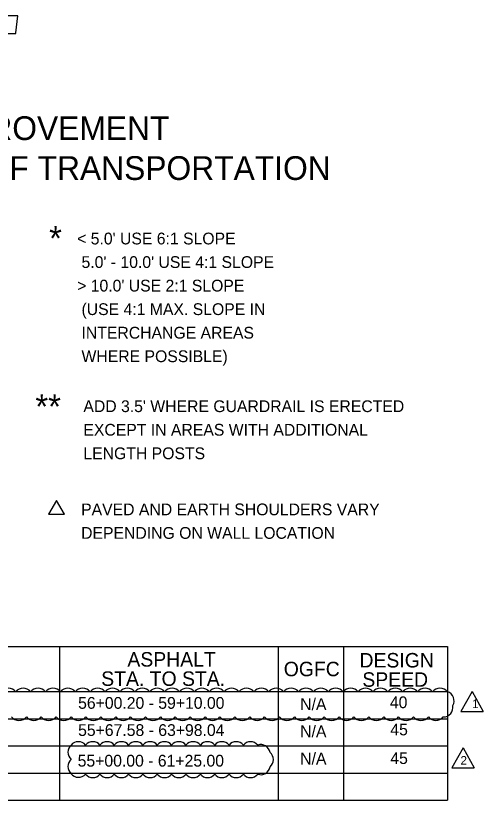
# Model space of a CAD drawing. Extents: x 5017 to 5774, y 4942 to 5266.
# Drawn here: x 5193.4 to 5241, y 5136.1 to 5216.1 of the extents above; entities that cross this region are included whole.
import ezdxf

# ---------------------------------------------------------------- set-up
doc = ezdxf.new("R2010")
doc.units = 0
for name, color, linetype in [('Level 40', 7, 'Continuous'), ('RD_SHT_Logo', 7, 'Continuous'), ('RD_SHT_TX', 7, 'Continuous'), ('RD_TX_TypSect', 7, 'Continuous')]:
    doc.layers.add(name, color=color, linetype=linetype)

msp = doc.modelspace()

# ---------------------------------------------------------------- linework, layer by layer
at = {"layer": 'Level 40'}
for p, q in [((5144.352, 5151.793), (5237.351, 5151.793)), ((5197.821, 5151.793), (5197.821, 5147.178)), ((5220.101, 5151.793), (5220.101, 5147.178)), ((5226.762, 5151.793), (5226.762, 5147.178)), ((5237.351, 5151.793), (5237.351, 5147.178))]:
    msp.add_line(p, q, dxfattribs=at)
at = {"layer": 'RD_SHT_Logo'}
msp.add_lwpolyline([(5192.072, 5214.257), (5193.325, 5214.257), (5193.369, 5214.271), (5193.383, 5214.286), (5193.383, 5214.329), (5193.602, 5216.077), (5193.602, 5216.077), (5193.573, 5216.077), (5193.558, 5216.077), (5193.442, 5216.063), (5193.281, 5216.063), (5188.635, 5216.048), (5188.547, 5216.048), (5188.533, 5216.048), (5188.518, 5216.034), (5188.504, 5215.975), (5188.343, 5215.276), (5188.125, 5214.286)], dxfattribs=at)
at = {"layer": 'RD_SHT_TX'}
for p, q in [((5239.849, 5147.201), (5238.71, 5145.171)), ((5239.849, 5147.201), (5240.987, 5145.171)), ((5238.71, 5145.171), (5240.987, 5145.171)), ((5238.926, 5141.437), (5237.787, 5139.408)), ((5238.926, 5141.437), (5240.065, 5139.408)), ((5237.787, 5139.408), (5240.065, 5139.408))]:
    msp.add_line(p, q, dxfattribs=at)
for centre, radius, start, end in [((5192.614, 5146.532), 0.989, 40, 140), ((5194.13, 5146.532), 0.989, 40, 140), ((5195.646, 5146.532), 0.989, 40, 140), ((5197.162, 5146.532), 0.989, 40, 140), ((5198.678, 5146.532), 0.989, 40, 140), ((5200.194, 5146.532), 0.989, 40, 140), ((5201.709, 5146.532), 0.989, 40, 140), ((5203.225, 5146.532), 0.989, 40, 140), ((5204.741, 5146.532), 0.989, 40, 140), ((5206.257, 5146.532), 0.989, 40, 140), ((5207.773, 5146.532), 0.989, 40, 140), ((5209.289, 5146.532), 0.989, 40, 140), ((5210.805, 5146.532), 0.989, 40, 140), ((5212.321, 5146.532), 0.989, 40, 140), ((5213.837, 5146.532), 0.989, 40, 140), ((5215.352, 5146.532), 0.989, 40, 140), ((5216.868, 5146.532), 0.989, 40, 140), ((5218.384, 5146.532), 0.989, 40, 140), ((5219.9, 5146.532), 0.989, 40, 140), ((5221.416, 5146.532), 0.989, 40, 140), ((5222.932, 5146.532), 0.989, 40, 140), ((5224.448, 5146.532), 0.989, 40, 140), ((5225.964, 5146.532), 0.989, 40, 140), ((5227.48, 5146.532), 0.989, 40, 140), ((5228.995, 5146.532), 0.989, 40, 140), ((5230.511, 5146.532), 0.989, 40, 140), ((5232.027, 5146.532), 0.989, 40, 140), ((5233.543, 5146.532), 0.989, 40, 140), ((5235.059, 5146.532), 0.989, 40, 140), ((5236.575, 5146.532), 0.989, 40, 140), ((5237.02, 5146.23), 0.989, 331.53931, 71.53931), ((5236.914, 5145.591), 0.989, 269.75671, 9.75671), ((5193.707, 5145.237), 0.989, 220, 320), ((5195.223, 5145.237), 0.989, 220, 320), ((5196.739, 5145.237), 0.989, 220, 320), ((5198.255, 5145.237), 0.989, 220, 320), ((5199.77, 5145.237), 0.989, 220, 320), ((5201.286, 5145.237), 0.989, 220, 320), ((5202.802, 5145.237), 0.989, 220, 320), ((5204.318, 5145.237), 0.989, 220, 320), ((5205.834, 5145.237), 0.989, 220, 320), ((5207.35, 5145.237), 0.989, 220, 320), ((5208.866, 5145.237), 0.989, 220, 320), ((5210.382, 5145.237), 0.989, 220, 320), ((5211.898, 5145.237), 0.989, 220, 320), ((5213.413, 5145.237), 0.989, 220, 320), ((5214.929, 5145.237), 0.989, 220, 320), ((5216.445, 5145.237), 0.989, 220, 320), ((5217.961, 5145.237), 0.989, 220, 320), ((5219.477, 5145.237), 0.989, 220, 320), ((5220.993, 5145.237), 0.989, 220, 320), ((5222.509, 5145.237), 0.989, 220, 320), ((5224.025, 5145.237), 0.989, 220, 320), ((5225.541, 5145.237), 0.989, 220, 320), ((5227.056, 5145.237), 0.989, 220, 320), ((5228.572, 5145.237), 0.989, 220, 320), ((5230.088, 5145.237), 0.989, 220, 320), ((5231.604, 5145.237), 0.989, 220, 320), ((5233.12, 5145.237), 0.989, 220, 320), ((5234.636, 5145.237), 0.989, 220, 320), ((5236.152, 5145.237), 0.989, 220, 320), ((5199.635, 5141), 0.954, 130, 230), ((5199.752, 5141.118), 0.954, 40, 140), ((5201.214, 5141.118), 0.954, 40, 140), ((5202.675, 5141.118), 0.954, 40, 140), ((5204.136, 5141.118), 0.954, 40, 140), ((5205.598, 5141.118), 0.954, 40, 140), ((5207.059, 5141.118), 0.954, 40, 140), ((5208.521, 5141.118), 0.954, 40, 140), ((5209.982, 5141.118), 0.954, 40, 140), ((5211.443, 5141.118), 0.954, 40, 140), ((5212.905, 5141.118), 0.954, 40, 140), ((5214.366, 5141.118), 0.954, 40, 140), ((5215.828, 5141.118), 0.954, 40, 140), ((5217.289, 5141.117), 0.954, 40, 140), ((5218.33, 5140.829), 0.954, 8.9774, 108.9774), ((5218.659, 5140.247), 0.954, 310, 50), ((5199.634, 5139.539), 0.953, 130, 230), ((5218.329, 5139.664), 0.954, 251.09574, 351.09574), ((5199.772, 5139.399), 0.955, 218.14133, 318.14133), ((5201.214, 5139.375), 0.954, 220, 320), ((5202.676, 5139.375), 0.954, 220, 320), ((5204.137, 5139.375), 0.954, 220, 320), ((5205.598, 5139.375), 0.954, 220, 320), ((5207.06, 5139.375), 0.954, 220, 320), ((5208.521, 5139.375), 0.954, 220, 320), ((5209.983, 5139.375), 0.954, 220, 320), ((5211.444, 5139.375), 0.954, 220, 320), ((5212.905, 5139.375), 0.954, 220, 320), ((5214.367, 5139.375), 0.954, 220, 320), ((5215.828, 5139.375), 0.954, 220, 320), ((5217.29, 5139.375), 0.954, 220, 320)]:
    msp.add_arc(centre, radius, start, end, dxfattribs=at)
at = {"layer": 'RD_TX_TypSect'}
for p, q in [((5144.352, 5147.178), (5237.351, 5147.178)), ((5197.821, 5147.178), (5197.821, 5136.102)), ((5220.101, 5147.178), (5220.101, 5136.102)), ((5226.762, 5147.178), (5226.762, 5136.102)), ((5237.351, 5147.178), (5237.351, 5136.102)), ((5144.352, 5144.409), (5237.351, 5144.409)), ((5144.352, 5141.64), (5237.351, 5141.64)), ((5144.352, 5138.871), (5237.351, 5138.871)), ((5144.352, 5136.102), (5237.351, 5136.102))]:
    msp.add_line(p, q, dxfattribs=at)
msp.add_lwpolyline([(5197.526, 5166.645), (5196.727, 5165.26), (5198.325, 5165.26)], close=True, dxfattribs=at)

# ---------------------------------------------------------------- texts
at = {"layer": 'RD_SHT_TX'}
for s, height, p in [('TYPICAL SECTION OF IMPROVEMENT', 2.42031, (5149.865, 5203.404)), ('SOUTH CAROLINA DEPARTMENT OF TRANSPORTATION', 2.42031, (5137.339, 5199.336)), ('1', 0.88, (5239.848, 5145.5)), ('2', 0.88, (5238.671, 5139.736))]:
    msp.add_text(s, height=height, dxfattribs=at).set_placement(p)
at = {"layer": 'RD_TX_TypSect'}
for s, height, p in [('*', 2.5, (5196.776, 5192.135)), ("< 5.0' USE 6:1 SLOPE", 1.1999, (5199.627, 5192.764)), (" 5.0' - 10.0' USE 4:1 SLOPE", 1.1999, (5199.627, 5190.364)), ("> 10.0' USE 2:1 SLOPE", 1.1999, (5199.627, 5187.964)), (' (USE 4:1 MAX. SLOPE IN', 1.1999, (5199.627, 5185.564)), (' INTERCHANGE AREAS', 1.1999, (5199.627, 5183.164)), (' WHERE POSSIBLE)', 1.1999, (5199.627, 5180.765)), ('**', 2.5, (5195.375, 5174.991)), ('PAVED AND EARTH SHOULDERS VARY ', 1.1999, (5200.033, 5165.154)), ('DEPENDING ON WALL LOCATION', 1.1999, (5200.033, 5162.755)), ('ASPHALT', 1.4768, (5204.745, 5149.731)), ('DESIGN', 1.4768, (5228.38, 5149.64)), ('OGFC', 1.4768, (5220.669, 5148.748)), ('STA. TO STA.', 1.4768, (5202.078, 5147.766)), ('SPEED', 1.4768, (5228.671, 5147.675)), ('56+00.20 - 59+10.00', 1.2, (5199.727, 5145.43)), ('N/A', 1.2, (5222.342, 5145.3)), ('40', 1.2, (5231.475, 5145.492)), ('55+67.58 - 63+98.04', 1.2, (5199.727, 5142.661)), ('N/A', 1.2, (5222.342, 5142.531)), ('45', 1.2, (5231.522, 5142.723)), ('N/A', 1.2, (5222.342, 5139.75)), ('45', 1.2, (5231.522, 5139.803)), ('55+00.00 - 61+25.00', 1.2, (5199.682, 5139.539))]:
    msp.add_text(s, height=height, dxfattribs=at).set_placement(p)
for s, p in [("ADD 3.5' WHERE GUARDRAIL IS ERECTED ", (5200.264, 5175.671)), ('EXCEPT IN AREAS WITH ADDITIONAL ', (5200.264, 5173.272)), ('LENGTH POSTS', (5200.264, 5170.872))]:
    msp.add_text(s, height=1.1999, rotation=360, dxfattribs=at).set_placement(p)

doc.saveas('drawing.dxf')
